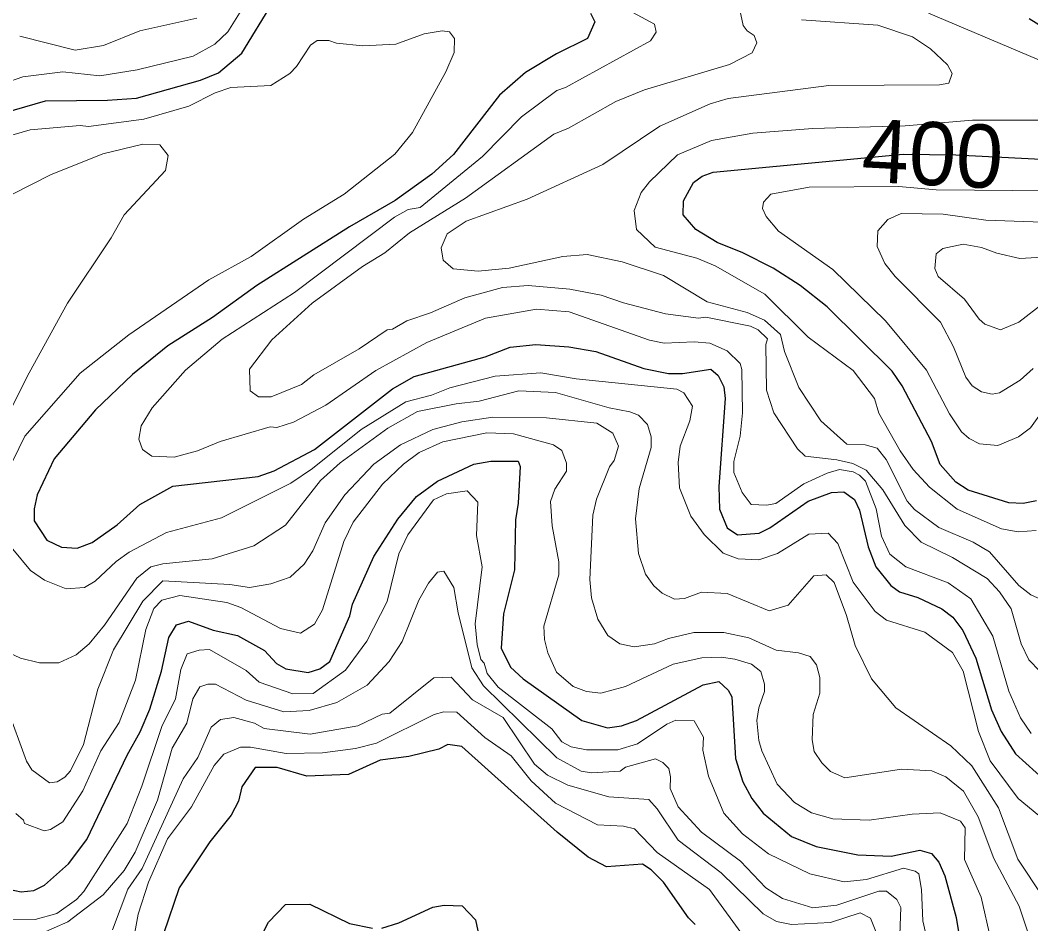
# Model space of a CAD drawing. Extents: x 673.3 to 698.5, y 6984.3 to 7012.3.
# Drawn here: x 686.64 to 687.92, y 6991.822 to 6992.967 of the extents above; entities that cross this region are included whole.
import ezdxf
from ezdxf.enums import TextEntityAlignment as Align

# ---------------------------------------------------------------- set-up
doc = ezdxf.new("R2010")
doc.units = 0
doc.header["$LTSCALE"] = 0.032
doc.layers.add('1', color=7, linetype='Continuous', lineweight=25)
doc.layers.add('2', color=7, linetype='Continuous', lineweight=13)
doc.layers.add('61', color=7, linetype='Continuous')

msp = doc.modelspace()

# ---------------------------------------------------------------- linework, layer by layer
at = {"layer": '1'}
for points in [[(686.6191, 6992.8492), (686.6718, 6992.8643), (686.75, 6992.8651), (686.7867, 6992.868), (686.868, 6992.8906), (686.8907, 6992.8998), (686.9204, 6992.9248), (686.9594, 6992.9889)], [(687.3618, 6992.9756), (687.3673, 6992.9647), (687.358, 6992.9432), (687.3188, 6992.9239), (687.2797, 6992.9003), (687.2466, 6992.8714), (687.1883, 6992.7963), (687.1611, 6992.7717), (687.1143, 6992.7384), (687.0565, 6992.7048), (686.9393, 6992.6307), (686.8831, 6992.59), (686.8266, 6992.554), (686.782, 6992.518), (686.735, 6992.4731), (686.6828, 6992.4108), (686.661, 6992.3653), (686.6573, 6992.3475), (686.6573, 6992.3326), (686.6733, 6992.3078), (686.6918, 6992.2991), (686.7116, 6992.2978), (686.7308, 6992.305), (686.7625, 6992.3272), (686.791, 6992.3531), (686.8331, 6992.3765)], [(687.4792, 6992.7199), (687.4797, 6992.7378), (687.4922, 6992.761), (687.5034, 6992.769), (687.5172, 6992.7739), (687.7579, 6992.7967), (687.8248, 6992.7961), (687.9326, 6992.7905), (687.9713, 6992.7955), (687.9865, 6992.8001), (688.0036, 6992.8091), (688.0331, 6992.8322), (688.0534, 6992.8609), (688.0613, 6992.8784), (688.0652, 6992.9018), (688.0565, 6992.9215), (688.0457, 6992.9246), (688.0088, 6992.923), (687.974, 6992.9333), (687.9173, 6992.9684)], [(687.9269, 6992.3576), (687.91, 6992.3546), (687.8916, 6992.3554), (687.8404, 6992.3714), (687.8247, 6992.3816), (687.8048, 6992.4039), (687.7936, 6992.4328), (687.7568, 6992.5033), (687.7438, 6992.522), (687.6616, 6992.6034), (687.6274, 6992.6304), (687.5932, 6992.6524), (687.5549, 6992.672), (687.5222, 6992.685), (687.4955, 6992.7013), (687.4792, 6992.7199)], [(686.8331, 6992.3765), (686.9409, 6992.3888), (686.9614, 6992.3958), (687.0125, 6992.4229), (687.111, 6992.4996), (687.1387, 6992.5154), (687.2286, 6992.5402), (687.2601, 6992.5525), (687.2926, 6992.5557), (687.3344, 6992.5528), (687.3686, 6992.5468), (687.4295, 6992.5255), (687.4605, 6992.5192), (687.4784, 6992.5191), (687.5145, 6992.5247), (687.5237, 6992.5165), (687.5309, 6992.5022), (687.5326, 6992.4874), (687.5246, 6992.3759), (687.5254, 6992.3473), (687.535, 6992.3236), (687.5482, 6992.3147), (687.5755, 6992.317), (687.5891, 6992.3237), (687.6375, 6992.3572), (687.6671, 6992.3683), (687.6826, 6992.3691), (687.6962, 6992.3593), (687.7027, 6992.3458), (687.7135, 6992.2997), (687.7233, 6992.2741), (687.7425, 6992.2505), (687.7531, 6992.2427), (687.7764, 6992.2355), (687.8068, 6992.2211), (687.8209, 6992.2103), (687.8335, 6992.1935), (687.8501, 6992.1585), (687.8697, 6992.0929), (687.8819, 6992.0657), (687.9003, 6992.0375), (687.9396, 6992.002)], [(686.8526, 6992.2053), (686.8839, 6992.194), (686.9148, 6992.1874), (686.9491, 6992.1683), (686.964, 6992.1519), (686.9761, 6992.1448), (687.0044, 6992.1404), (687.0191, 6992.145), (687.0318, 6992.1543), (687.057, 6992.212), (687.0605, 6992.2269), (687.0874, 6992.2872), (687.1177, 6992.3344), (687.1415, 6992.3632), (687.168, 6992.3827), (687.2142, 6992.4042), (687.2357, 6992.4082), (687.2701, 6992.4082), (687.2728, 6992.4014), (687.2704, 6992.355), (687.2669, 6992.3339), (687.2655, 6992.2703), (687.2518, 6992.2148), (687.2488, 6992.1712), (687.2607, 6992.1469), (687.2767, 6992.1323), (687.3508, 6992.0794), (687.3834, 6992.0704), (687.4012, 6992.0727), (687.4201, 6992.0795), (687.5044, 6992.1249), (687.5243, 6992.1289), (687.5361, 6992.1181), (687.5409, 6992.1096), (687.5457, 6992.0315), (687.5548, 6992.002), (687.5661, 6991.9808), (687.5808, 6991.962), (687.6165, 6991.9327), (687.6479, 6991.9201), (687.7005, 6991.9094), (687.7427, 6991.9075), (687.7792, 6991.9155), (687.7937, 6991.911), (687.803, 6991.9001), (687.8106, 6991.8827), (687.8249, 6991.8299), (687.834, 6991.7758)], [(686.6247, 6991.866), (686.6406, 6991.8627), (686.6569, 6991.8642), (686.6705, 6991.8709), (686.7006, 6991.8979), (686.7241, 6991.9289), (686.7752, 6992.0358), (686.7915, 6992.0651), (686.8036, 6992.0941), (686.8185, 6992.1422), (686.8279, 6992.1847), (686.8375, 6992.2007), (686.8526, 6992.2053)], [(687.4944, 6991.8213), (687.486, 6991.8298), (687.4544, 6991.8748), (687.4388, 6991.8904), (687.4276, 6991.8975), (687.382, 6991.8944), (687.3591, 6991.9066), (687.3195, 6991.9381), (687.199, 6992.0464), (687.1814, 6992.049), (687.1699, 6992.0434), (687.132, 6992.0338), (687.0953, 6992.0295), (687.0555, 6992.0113), (687.0028, 6992.0092), (686.965, 6992.0198), (686.9372, 6992.0199), (686.9204, 6991.9956), (686.9161, 6991.9774), (686.9066, 6991.9598), (686.8797, 6991.926), (686.8408, 6991.8674), (686.8209, 6991.8094)], [(686.9326, 6991.7823), (686.9541, 6991.8241), (686.9754, 6991.8464), (687.0065, 6991.8471), (687.0567, 6991.8224), (687.086, 6991.8164)], [(687.0977, 6991.8163), (687.1191, 6991.8233), (687.1624, 6991.8432), (687.1765, 6991.8455), (687.1995, 6991.8446), (687.2164, 6991.8269), (687.219, 6991.813)]]:
    msp.add_lwpolyline(points, dxfattribs=at)
at = {"layer": '2'}
for points in [[(687.3709, 6993.001), (687.4431, 6992.9616), (687.4451, 6992.9516), (687.4377, 6992.9404), (687.3302, 6992.8815), (687.3192, 6992.8775), (687.2743, 6992.844), (687.2252, 6992.7938), (687.146, 6992.7293), (687.131, 6992.7268), (687.1137, 6992.7172), (686.987, 6992.6218), (686.8954, 6992.5625), (686.8488, 6992.5232), (686.8069, 6992.4756), (686.793, 6992.4529), (686.79, 6992.4358), (686.7943, 6992.4226), (686.8064, 6992.4145), (686.8344, 6992.4131), (686.864, 6992.4209), (686.8927, 6992.433), (686.9561, 6992.4513), (686.9647, 6992.4506), (686.9856, 6992.4575), (687.0267, 6992.4789), (687.0902, 6992.5229), (687.1548, 6992.5585), (687.2289, 6992.589), (687.2937, 6992.6005), (687.3347, 6992.5971), (687.4367, 6992.5611), (687.4551, 6992.5573), (687.4934, 6992.559)], [(686.6187, 6992.8865), (686.643, 6992.8947), (686.6937, 6992.901), (686.7405, 6992.8961), (686.7878, 6992.9035), (686.8588, 6992.9212), (686.8859, 6992.9361), (686.9027, 6992.9519), (686.9217, 6992.9822)], [(686.639, 6992.9464), (686.7091, 6992.9287), (686.7451, 6992.9344), (686.791, 6992.9531), (686.8634, 6992.9691)], [(687.5512, 6992.9798), (687.5552, 6992.9599), (687.5603, 6992.953), (687.5694, 6992.9471), (687.5725, 6992.938), (687.5665, 6992.9253), (687.5381, 6992.9106), (687.4302, 6992.8785), (687.394, 6992.8637), (687.3342, 6992.8297), (687.3156, 6992.822), (687.2036, 6992.7411), (687.1328, 6992.6973), (687.1016, 6992.672), (687.0733, 6992.6544), (687.0095, 6992.6081), (686.9583, 6992.5619), (686.9301, 6992.5245), (686.9309, 6992.4971), (686.9416, 6992.4894), (686.9576, 6992.4895), (686.9958, 6992.505), (687.0115, 6992.5173), (687.0688, 6992.5504)], [(687.7902, 6992.9753), (687.9384, 6992.9127)], [(687.6291, 6992.967), (687.7259, 6992.9603), (687.7699, 6992.9456), (687.7927, 6992.9301), (687.8142, 6992.9101), (687.8199, 6992.8989), (687.8157, 6992.887), (687.8038, 6992.8846), (687.6636, 6992.8838), (687.5361, 6992.8674), (687.5133, 6992.8608), (687.4498, 6992.8322), (687.3774, 6992.7838), (687.2816, 6992.7399), (687.2044, 6992.712), (687.1803, 6992.6958), (687.1728, 6992.6781), (687.1751, 6992.6626), (687.1881, 6992.6515), (687.2197, 6992.6485), (687.2588, 6992.6523), (687.3269, 6992.6673), (687.3578, 6992.6696), (687.4018, 6992.6607), (687.4543, 6992.6431), (687.5097, 6992.6099), (687.5605, 6992.5965), (687.5823, 6992.5865), (687.6027, 6992.5683), (687.6077, 6992.5469)], [(686.6301, 6992.4085), (686.6454, 6992.4395), (686.7155, 6992.5195), (686.7771, 6992.568), (686.8785, 6992.6377), (686.9321, 6992.6672), (686.9983, 6992.7144), (687.0497, 6992.7463), (687.1141, 6992.7969), (687.1364, 6992.8242), (687.1785, 6992.9012), (687.1893, 6992.9255), (687.1897, 6992.9433), (687.1833, 6992.952), (687.1739, 6992.9531), (687.1513, 6992.9491), (687.1152, 6992.9361), (687.0736, 6992.9339), (687.0402, 6992.9375), (687.0304, 6992.941), (687.0156, 6992.9408), (687.0074, 6992.9351), (686.9896, 6992.9078), (686.9809, 6992.899), (686.957, 6992.884), (686.9064, 6992.8814), (686.8866, 6992.8747), (686.853, 6992.8577), (686.7963, 6992.8412), (686.7262, 6992.8318), (686.7155, 6992.8332), (686.6521, 6992.8276), (686.5953, 6992.8113)], [(687.9328, 6992.8399), (687.8456, 6992.8398), (687.7606, 6992.8326), (687.6435, 6992.8292), (687.5674, 6992.8235), (687.5151, 6992.8142), (687.4722, 6992.7962), (687.4365, 6992.7619), (687.4261, 6992.7484), (687.4172, 6992.7255), (687.4203, 6992.7015), (687.4438, 6992.6789), (687.4964, 6992.6651), (687.5198, 6992.6553), (687.5826, 6992.6197), (687.6374, 6992.565), (687.6947, 6992.523), (687.7215, 6992.4872), (687.7273, 6992.4687), (687.7541, 6992.4211), (687.7707, 6992.3974), (687.7914, 6992.3752), (687.8262, 6992.3473), (687.8825, 6992.3223), (687.9037, 6992.3187), (687.9264, 6992.3203)], [(686.6298, 6992.7464), (686.6781, 6992.7706), (686.7443, 6992.7975), (686.795, 6992.8097), (686.8165, 6992.8089), (686.8272, 6992.7953), (686.8238, 6992.776), (686.7714, 6992.72), (686.7549, 6992.6909), (686.6997, 6992.608), (686.6508, 6992.5201), (686.626, 6992.4703)], [(687.9317, 6992.4678), (687.9191, 6992.4503), (687.9041, 6992.4388), (687.8778, 6992.4279), (687.8548, 6992.4301), (687.8413, 6992.4368), (687.832, 6992.4452), (687.8168, 6992.4679), (687.7875, 6992.5231), (687.7354, 6992.5858), (687.6689, 6992.6507), (687.6, 6992.6992), (687.5845, 6992.7181), (687.5799, 6992.7281), (687.5809, 6992.7359), (687.5901, 6992.7462), (687.639, 6992.7551), (687.7526, 6992.7561), (687.7999, 6992.7518), (687.9455, 6992.7505)], [(688.0179, 6992.7079), (687.8626, 6992.7132), (687.8087, 6992.7209), (687.7554, 6992.7217), (687.7386, 6992.7143), (687.726, 6992.6996), (687.7248, 6992.6798), (687.7347, 6992.6584), (687.7476, 6992.6419), (687.805, 6992.5839), (687.8216, 6992.5527), (687.8374, 6992.5143), (687.8453, 6992.5036), (687.857, 6992.4958), (687.8706, 6992.493), (687.8798, 6992.4944), (687.9062, 6992.5107), (687.9224, 6992.5252)], [(687.0688, 6992.5504), (687.1044, 6992.5742), (687.1113, 6992.5752), (687.1293, 6992.5856), (687.1594, 6992.5958), (687.2028, 6992.615), (687.2503, 6992.6282), (687.2831, 6992.6306), (687.3358, 6992.6257), (687.3752, 6992.6184), (687.4038, 6992.6084), (687.4567, 6992.5948), (687.4985, 6992.5891), (687.508, 6992.5905), (687.5647, 6992.5791), (687.5742, 6992.5743), (687.5862, 6992.563), (687.5838, 6992.5557), (687.5847, 6992.4979), (687.5939, 6992.4691), (687.6241, 6992.4235), (687.6339, 6992.4143), (687.674, 6992.4099), (687.6942, 6992.4049), (687.7112, 6992.3966), (687.732, 6992.3718), (687.76, 6992.3266), (687.7805, 6992.3053), (687.8204, 6992.2859), (687.8641, 6992.2592), (687.8799, 6992.2425), (687.8949, 6992.2211), (687.9072, 6992.1768), (687.9172, 6992.1564), (687.9308, 6992.1419)], [(687.4934, 6992.559), (687.513, 6992.5573), (687.5349, 6992.5478), (687.5513, 6992.5319), (687.5536, 6992.5241), (687.5546, 6992.4691), (687.5513, 6992.4398), (687.5433, 6992.4077), (687.5433, 6992.3937), (687.5538, 6992.3682), (687.5653, 6992.3532), (687.5848, 6992.3521), (687.5967, 6992.3545), (687.6323, 6992.3794), (687.6616, 6992.3928), (687.6774, 6992.3973), (687.6944, 6992.3944), (687.7027, 6992.3902), (687.7102, 6992.3825), (687.7238, 6992.3478), (687.7305, 6992.313), (687.7412, 6992.2901), (687.7613, 6992.274), (687.8147, 6992.2538), (687.8437, 6992.2338), (687.8713, 6992.1862), (687.8919, 6992.1169), (687.9066, 6992.0831), (687.9202, 6992.0631)], [(687.6077, 6992.5469), (687.6257, 6992.5013), (687.6536, 6992.459), (687.6866, 6992.4295), (687.7097, 6992.4286), (687.725, 6992.4243), (687.7365, 6992.4101), (687.7628, 6992.3575), (687.7723, 6992.3469), (687.8032, 6992.324), (687.8465, 6992.3055), (687.8674, 6992.293), (687.9043, 6992.2507), (687.9195, 6992.2389), (687.932, 6992.2332)], [(687.2992, 6992.5198), (687.2413, 6992.5156), (687.1838, 6992.5007), (687.1604, 6992.4916), (687.1282, 6992.4832), (687.0715, 6992.448), (687.01, 6992.3986), (686.9824, 6992.3802), (686.8944, 6992.3363), (686.8247, 6992.3177), (686.7776, 6992.2928), (686.7611, 6992.2811), (686.7347, 6992.2561), (686.7212, 6992.2479), (686.6977, 6992.2462), (686.6705, 6992.2574), (686.6527, 6992.2694), (686.6302, 6992.2965)], [(687.937, 6991.9533), (687.9036, 6991.9809), (687.8679, 6992.0285), (687.8532, 6992.0658), (687.8339, 6992.1419), (687.8206, 6992.1657), (687.7854, 6992.1915), (687.7368, 6992.2068), (687.7224, 6992.2177), (687.6946, 6992.2546), (687.6752, 6992.3038), (687.6631, 6992.3167), (687.6383, 6992.3155), (687.5986, 6992.2909), (687.5753, 6992.2831), (687.5488, 6992.2843), (687.53, 6992.2915), (687.5059, 6992.3152), (687.489, 6992.3384), (687.4746, 6992.3743), (687.4731, 6992.4062), (687.4755, 6992.4269), (687.4879, 6992.4593), (687.491, 6992.4777), (687.4803, 6992.4947), (687.4711, 6992.4994), (687.3439, 6992.5125), (687.2992, 6992.5198)], [(686.6176, 6992.1691), (686.6399, 6992.1584), (686.664, 6992.1525), (686.6887, 6992.1527), (686.7106, 6992.1626), (686.727, 6992.1767), (686.7463, 6992.2002), (686.7874, 6992.26), (686.8049, 6992.2743), (686.8202, 6992.2779), (686.8827, 6992.2842), (686.9357, 6992.3007), (686.9758, 6992.327), (687.02, 6992.3835), (687.045, 6992.406), (687.1051, 6992.4497), (687.1426, 6992.4709), (687.1917, 6992.4808), (687.221, 6992.484), (687.2712, 6992.497), (687.3174, 6992.4952), (687.3855, 6992.4754), (687.4119, 6992.4707), (687.4225, 6992.4661), (687.4342, 6992.4544), (687.4389, 6992.4387), (687.4389, 6992.4254), (687.4236, 6992.3735), (687.4187, 6992.3349), (687.4229, 6992.2912), (687.4314, 6992.2647), (687.4422, 6992.2502), (687.4528, 6992.2409), (687.4681, 6992.2333), (687.4811, 6992.2339), (687.5026, 6992.2421), (687.5348, 6992.2405), (687.5882, 6992.2185), (687.6124, 6992.2256), (687.6448, 6992.2629), (687.6602, 6992.264), (687.6706, 6992.2542), (687.6863, 6992.2126), (687.6972, 6992.1745), (687.7176, 6992.1322), (687.7488, 6992.0956), (687.8183, 6992.0476), (687.8447, 6992.022), (687.8788, 6991.9691), (687.9033, 6991.9039), (687.935, 6991.8562)], [(687.3694, 6992.3598), (687.3859, 6992.4007), (687.392, 6992.4088), (687.3974, 6992.427), (687.3901, 6992.4433), (687.3699, 6992.4562), (687.306, 6992.4628), (687.2383, 6992.4636), (687.1991, 6992.4579), (687.1621, 6992.4481), (687.1212, 6992.4285), (687.0875, 6992.4043), (687.0509, 6992.3654), (687.026, 6992.3298), (687.0103, 6992.2945), (686.9994, 6992.2774), (686.9816, 6992.2611), (686.9569, 6992.2526), (686.9302, 6992.2479), (686.9051, 6992.2518), (686.8201, 6992.2566), (686.795, 6992.2307), (686.7578, 6992.169), (686.7379, 6992.1194), (686.7198, 6992.0491), (686.7032, 6992.016), (686.6962, 6992.0076), (686.6862, 6992.0018), (686.6766, 6992.0004), (686.6542, 6992.017), (686.6476, 6992.028), (686.6228, 6992.0966)], [(686.634, 6991.9616), (686.6439, 6991.9531), (686.6452, 6991.949), (686.67, 6991.94), (686.6778, 6991.9413), (686.6936, 6991.9512), (686.7189, 6991.9903), (686.7417, 6992.0412), (686.7651, 6992.077), (686.7858, 6992.1305), (686.7986, 6992.1948), (686.809, 6992.2215), (686.819, 6992.2321), (686.8417, 6992.2379), (686.9013, 6992.2291), (686.9189, 6992.2228), (686.9692, 6992.1961), (686.9945, 6992.1901), (687.0122, 6992.2014), (687.0223, 6992.2199), (687.0496, 6992.3061), (687.0615, 6992.3306), (687.0985, 6992.3789), (687.1249, 6992.4043), (687.1451, 6992.4188), (687.1748, 6992.4327), (687.2308, 6992.4441), (687.2644, 6992.4425), (687.315, 6992.4287), (687.3255, 6992.4214), (687.3315, 6992.4054), (687.3314, 6992.3955), (687.3166, 6992.3727), (687.3112, 6992.3571), (687.3135, 6992.326), (687.3217, 6992.2807), (687.3217, 6992.2642), (687.303, 6992.1992), (687.3037, 6992.182), (687.3077, 6992.1653), (687.3189, 6992.1408), (687.3401, 6992.1226), (687.3569, 6992.1164), (687.3748, 6992.1143), (687.4061, 6992.1225), (687.4667, 6992.1508), (687.5028, 6992.1591), (687.5272, 6992.1598), (687.5449, 6992.1574), (687.5658, 6992.1508), (687.5775, 6992.1415), (687.5823, 6992.1256), (687.5823, 6992.1162), (687.5752, 6992.0957), (687.5726, 6992.0794), (687.575, 6992.0541), (687.5787, 6992.0413), (687.5985, 6991.9989), (687.6202, 6991.9755), (687.6416, 6991.9625), (687.669, 6991.955), (687.715, 6991.9531), (687.7694, 6991.9611), (687.8047, 6991.9628), (687.8305, 6991.9521), (687.8364, 6991.9437), (687.8356, 6991.9034), (687.8566, 6991.8556), (687.8688, 6991.8018)], [(687.8102, 6991.706), (687.7827, 6991.8258), (687.781, 6991.8653), (687.7776, 6991.8854), (687.7731, 6991.8888), (687.7583, 6991.8926), (687.7113, 6991.8781), (687.6832, 6991.875), (687.6396, 6991.8853), (687.5875, 6991.9105), (687.5546, 6991.936), (687.5309, 6991.9622), (687.5113, 6992.009), (687.5042, 6992.0419), (687.5049, 6992.0586), (687.4931, 6992.0792), (687.47, 6992.08), (687.4586, 6992.0751), (687.4214, 6992.0501), (687.3964, 6992.0425), (687.3567, 6992.0424), (687.3376, 6992.0463), (687.3255, 6992.0526), (687.313, 6992.0691), (687.2449, 6992.1218), (687.2309, 6992.1391), (687.2272, 6992.1522), (687.2231, 6992.1569), (687.2183, 6992.1759), (687.2158, 6992.2018), (687.2248, 6992.2743), (687.2175, 6992.314), (687.2191, 6992.3559), (687.2059, 6992.3706), (687.1794, 6992.3665), (687.163, 6992.3592), (687.1305, 6992.3149)], [(687.9161, 6991.81), (687.9047, 6991.8442), (687.8728, 6991.9047), (687.8529, 6991.9574), (687.8343, 6991.99), (687.8119, 6992.0083), (687.7941, 6992.0157), (687.756, 6992.0181), (687.6841, 6992.0068), (687.6659, 6992.015), (687.6547, 6992.0258), (687.6451, 6992.0402), (687.6426, 6992.055), (687.6441, 6992.0873), (687.6523, 6992.1142), (687.6523, 6992.1341), (687.6483, 6992.1499), (687.64, 6992.1607), (687.6253, 6992.1654), (687.5971, 6992.1688), (687.5623, 6992.1844), (687.5308, 6992.1908), (687.4927, 6992.1908), (687.4605, 6992.1835), (687.443, 6992.1767), (687.4172, 6992.173), (687.3989, 6992.1767), (687.3839, 6992.1872), (687.3711, 6992.2077), (687.3632, 6992.2351), (687.3609, 6992.2583), (687.3649, 6992.3396), (687.3694, 6992.3598)], [(687.1305, 6992.3149), (687.1192, 6992.2908), (687.1043, 6992.2302), (687.0786, 6992.18), (687.0516, 6992.1432), (687.0107, 6992.1136), (686.9849, 6992.1134), (686.9423, 6992.1281), (686.9256, 6992.1428), (686.8792, 6992.1696), (686.8662, 6992.1686), (686.8511, 6992.1639), (686.843, 6992.1443), (686.8361, 6992.1071), (686.8191, 6992.072), (686.7938, 6991.9964), (686.7749, 6991.9491), (686.7203, 6991.8629), (686.7107, 6991.8527), (686.686, 6991.835), (686.6586, 6991.8275), (686.6261, 6991.8269)], [(686.6479, 6991.8017), (686.6998, 6991.8245), (686.7447, 6991.8589), (686.7714, 6991.8897), (686.7852, 6991.9126), (686.8133, 6991.9785), (686.8321, 6992.0443), (686.8507, 6992.0762), (686.8581, 6992.1071), (686.8672, 6992.1222), (686.8772, 6992.1256), (686.887, 6992.1255), (686.9259, 6992.1051), (686.9735, 6992.0906), (687.0055, 6992.0922), (687.0405, 6992.1023), (687.0792, 6992.1242), (687.1071, 6992.1544), (687.1232, 6992.1797), (687.1443, 6992.2318), (687.1566, 6992.2533), (687.168, 6992.2673), (687.1761, 6992.2688), (687.1889, 6992.248), (687.1941, 6992.2158), (687.2115, 6992.1464), (687.2264, 6992.1234), (687.3192, 6992.0321), (687.3502, 6992.0152), (687.3633, 6992.0133), (687.3995, 6992.0154), (687.4064, 6992.0204), (687.4443, 6992.0311), (687.4534, 6992.0264), (687.461, 6992.0187), (687.4634, 6992.0082), (687.4627, 6991.9933), (687.4728, 6991.9702), (687.5023, 6991.9379), (687.5519, 6991.9013), (687.5838, 6991.8676), (687.6049, 6991.8539), (687.6434, 6991.8423), (687.6739, 6991.8455), (687.7273, 6991.8634), (687.7368, 6991.8634), (687.7497, 6991.8527), (687.7549, 6991.8427), (687.7533, 6991.7967)], [(687.724, 6991.81), (687.7166, 6991.8292), (687.7034, 6991.8358), (687.6657, 6991.8236), (687.6163, 6991.8211), (687.5973, 6991.8251), (687.5805, 6991.8346), (687.5275, 6991.8864), (687.4731, 6991.9279), (687.4465, 6991.9675), (687.4357, 6991.9793), (687.385, 6991.9828), (687.3334, 6991.9976), (687.3073, 6992.0104), (687.2911, 6992.0244), (687.2514, 6992.0835), (687.2123, 6992.1058), (687.1854, 6992.1346), (687.1636, 6992.1336), (687.1077, 6992.089), (687.0982, 6992.0874), (687.0674, 6992.0728), (687.0067, 6992.0622), (686.9484, 6992.0693), (686.9362, 6992.0761), (686.9102, 6992.0833), (686.8932, 6992.0806), (686.8814, 6992.0712), (686.8647, 6992.0326), (686.8461, 6992.0057), (686.7941, 6991.8921), (686.7758, 6991.8661), (686.7566, 6991.8146)], [(686.7809, 6991.7899), (686.7892, 6991.8344), (686.8021, 6991.8746), (686.8262, 6991.9297), (686.8564, 6991.9703), (686.8853, 6992.0225), (686.8977, 6992.0369), (686.9188, 6992.0457), (686.9311, 6992.0458), (686.9764, 6992.0377), (687.0226, 6992.0386), (687.0641, 6992.0442), (687.0909, 6992.0507), (687.1637, 6992.0873), (687.1762, 6992.0907), (687.1928, 6992.0899), (687.2279, 6992.0579), (687.2613, 6992.0346), (687.2869, 6992.0033), (687.3175, 6991.9748), (687.3709, 6991.9473), (687.4038, 6991.9456), (687.4176, 6991.9425), (687.4465, 6991.9125), (687.5126, 6991.8655), (687.5602, 6991.8002)]]:
    msp.add_lwpolyline(points, dxfattribs=at)
msp.add_lwpolyline([(687.936, 6992.6087), (688.0091, 6992.6454), (688.014, 6992.6565), (688.0082, 6992.6663), (687.9771, 6992.6689), (687.9058, 6992.6648), (687.8765, 6992.6714), (687.8572, 6992.6787), (687.8341, 6992.6827), (687.8081, 6992.6773), (687.7995, 6992.6707), (687.7982, 6992.6521), (687.8024, 6992.642), (687.8356, 6992.6134), (687.8542, 6992.5877), (687.8614, 6992.5814), (687.881, 6992.5744), (687.9046, 6992.584)], close=True, dxfattribs=at)

# ---------------------------------------------------------------- texts
at = {"layer": '61'}
msp.add_text('400', height=0.08, rotation=357.043, dxfattribs=at).set_placement((687.7932, 6992.7576), align=Align.CENTER)

doc.saveas('drawing.dxf')
